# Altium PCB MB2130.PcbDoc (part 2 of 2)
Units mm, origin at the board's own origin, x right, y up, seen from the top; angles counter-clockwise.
Board outline 43 x 51.11 mm, 4 copper layers (Top Layer, Signal Layer 1, Signal Layer 2, Bottom Layer), stack 1.592 mm thick; 94 components, 90 nets, 382 pads, 433 vias.
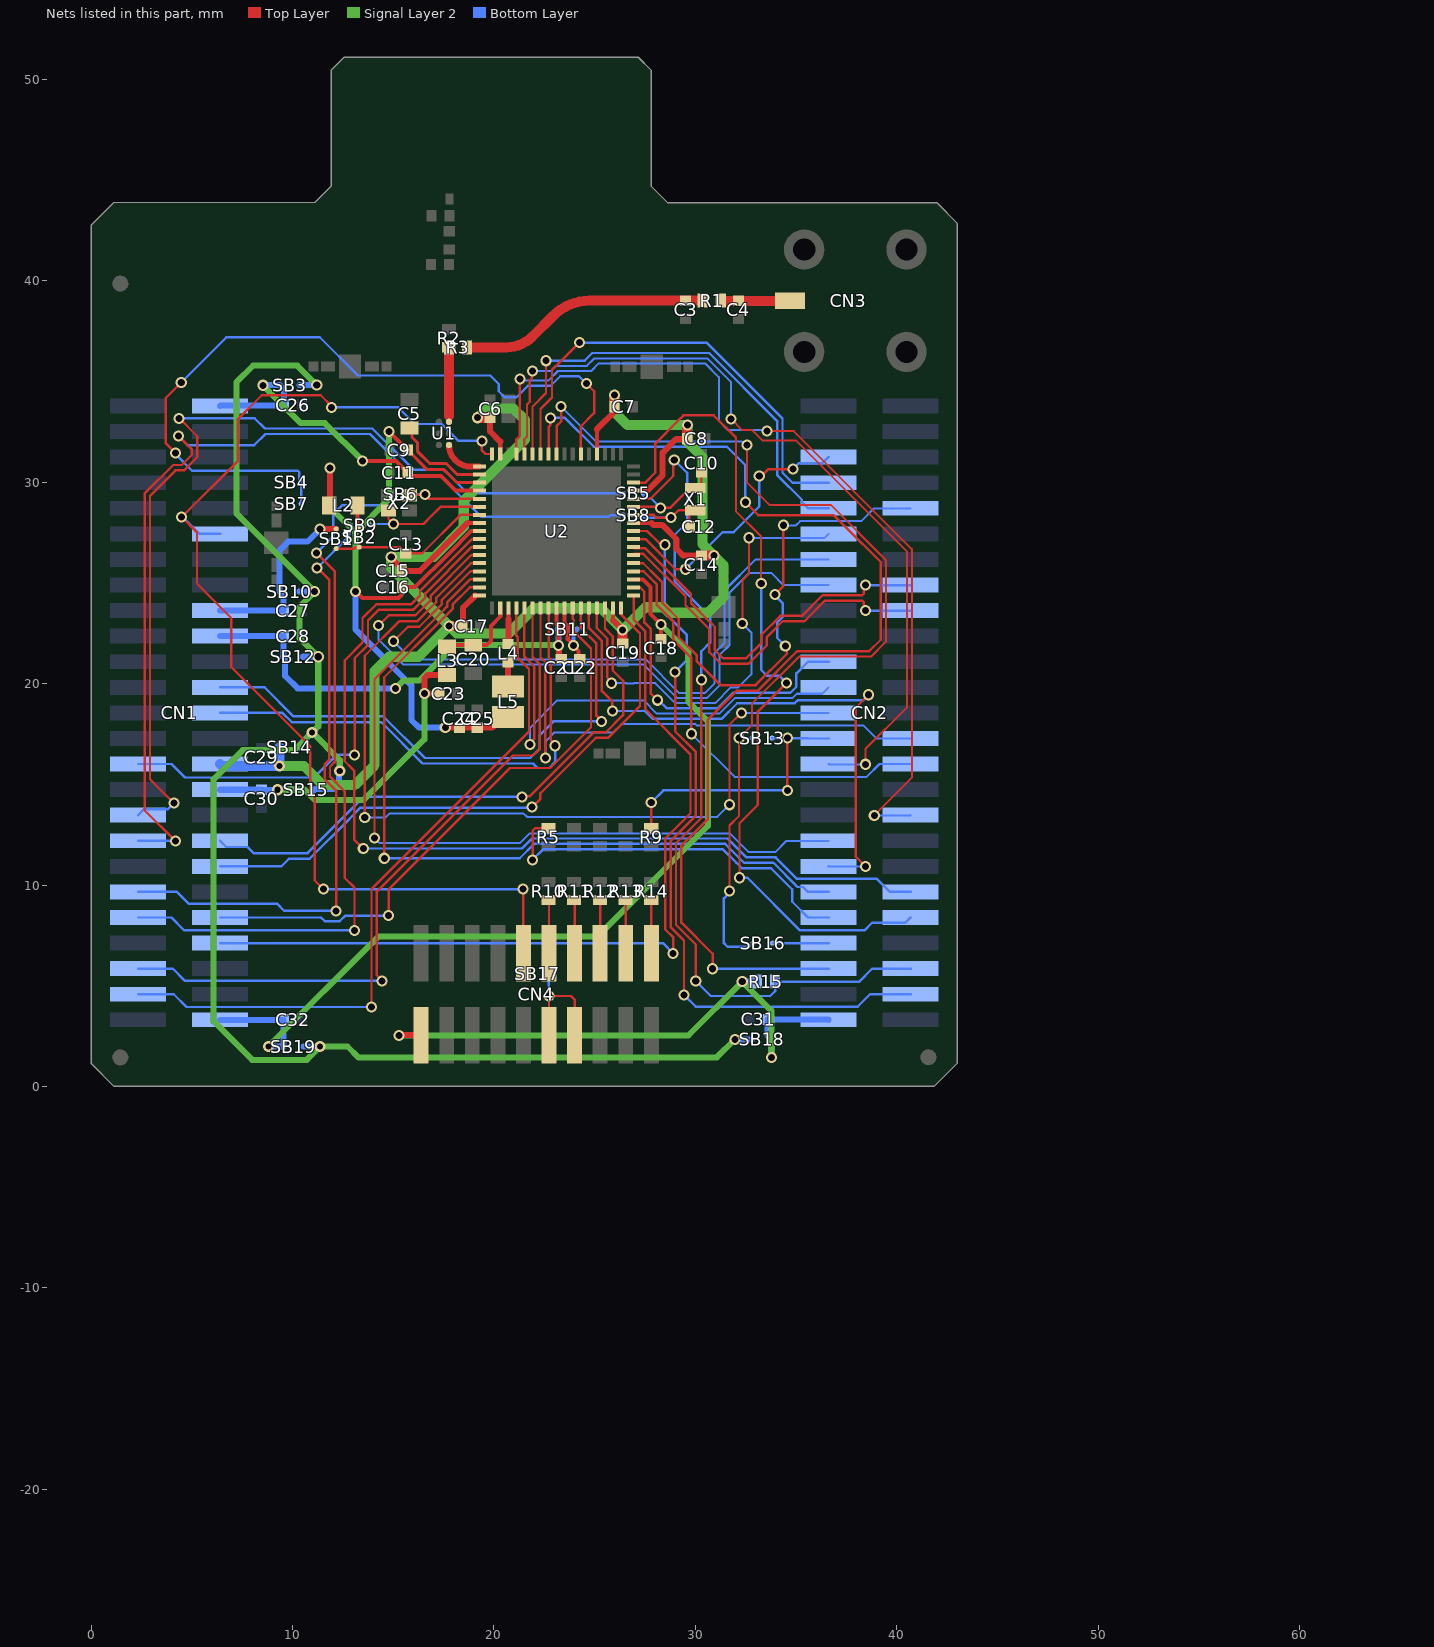
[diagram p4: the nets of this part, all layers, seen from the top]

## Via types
v1: diameter 0.55, hole 0.35, Top Layer to Bottom Layer, tented both sides, 425 vias
v2: diameter 0.55, hole 0.3, Top Layer to Bottom Layer, tented both sides, 8 vias

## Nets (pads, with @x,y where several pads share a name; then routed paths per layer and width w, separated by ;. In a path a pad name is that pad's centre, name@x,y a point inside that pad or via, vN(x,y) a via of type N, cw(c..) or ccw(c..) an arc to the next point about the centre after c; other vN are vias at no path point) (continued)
GPIO11: CN1.24 U2.12 | length 27.6
  Top Layer w0.12: U2.12@24.314,23.755 24.314,22.771 25.091,21.994 25.091,18.411 25.349,18.152 v1(25.349,18.126)
  Bottom Layer w0.12: CN1.24@6.401,19.818 8.613,19.818 10.056,18.376 14.505,18.376 16.574,16.307 21.805,16.307 22.282,16.785 22.282,17.455 22.953,18.126 v1(25.349,18.126)
GPIO12: CN1.26 U2.8 | length 25.7
  Top Layer w0.12: U2.8@22.714,23.755 22.714,21.317 22.822,21.209 22.822,17.589 22.825,17.586 22.825,17.202 23.035,16.991 v1@23.035,16.921
  Bottom Layer w0.12: CN1.26@6.401,18.548 9.501,18.548 9.965,18.085 14.414,18.085 16.462,16.037 21.942,16.037 22.167,15.812 22.746,15.812 23.04,16.106 v1(23.04,16.916)
GPIO14: CN1.29 U2.62 | length 25.6
  Top Layer w0.12: v1(13.081,16.459) 13.081,21.26 13.745,21.924 13.745,23.14 14.269,23.663 15.988,23.663 16.598,24.273 16.598,24.485 18.894,26.78 U2.62@19.289,26.78
  Bottom Layer w0.12: CN1.29@2.331,16.008 3.985,16.008 4.652,15.342 11.074,15.342 12.192,16.459 v1(13.081,16.459)
GPIO15/OSC32_IN: CN1.33 SB5.2 | length 46.8
  Top Layer w0.12: v1(4.109,14.064) 2.922,15.251 2.922,29.326 4.185,30.589 4.608,30.589 5.271,31.253 5.271,32.288 v1@4.377,33.183
  Bottom Layer w0.12: CN1.33@2.331,13.468 2.63,13.767 3.812,13.767 v1(4.109,14.064) ; v1(4.37,33.176) 8.118,33.176 8.625,32.668 13.959,32.668 16,30.627 17.515,30.627 18.687,29.455 26.427,29.455 SB5.2@26.439,29.442
GPIO16/OSC32_OUT: CN1.35 SB8.2 | length 48.4
  Top Layer w0.12: v1(4.184,12.185) 2.652,13.717 2.652,29.438 4.073,30.859 4.496,30.859 5.001,31.365 5.001,31.629 4.336,32.295 v1@4.332,32.295
  Bottom Layer w0.12: CN1.35@2.331,12.198 4.185,12.198 v1@4.191,12.192 ; v1(4.329,32.287) 4.778,31.838 8.089,31.838 8.649,32.398 13.847,32.398 15.943,30.302 17.351,30.302 19.358,28.295 25.715,28.295 25.792,28.372 SB8.2@26.424,28.372
GPIO17: CN1.36 U2.15 | length 28.8
  Top Layer w0.12: v1(21.387,14.376) 21.411,14.401 21.766,14.401 24.942,17.577 25.551,17.577 26.414,18.44 26.414,20.144 25.901,20.658 25.901,22.346 25.514,22.732 U2.15@25.514,23.755
  Bottom Layer w0.12: CN1.36@6.401,12.198 6.711,11.888 7.757,11.888 8.063,11.582 10.745,11.582 12.56,13.397 12.56,13.404 13.533,14.376 v1(21.387,14.376)
GPIO18: CN1.38 U2.17 | length 29.6
  Top Layer w0.12: v1(21.895,13.868) 22.306,14.28 22.306,14.559 25.054,17.307 25.663,17.307 27.254,18.898 27.254,22.486 26.927,22.813 26.354,23.386 26.354,23.715 U2.17@26.314,23.755
  Bottom Layer w0.12: CN1.38@6.401,10.928 9.443,10.928 9.817,11.303 10.466,11.303 10.475,11.312 10.857,11.312 12.83,13.285 12.83,13.292 13.381,13.843 21.151,13.843 21.869,13.843 v1(21.895,13.868)
GPIO21: CN1.42 U2.11 | length 29.6
  Top Layer w0.12: v1@14.783,8.484 14.783,9.8 20.795,15.812 22.795,15.812 24.821,17.837 24.821,21.739 23.976,22.584 23.976,23.152 23.914,23.215 U2.11@23.914,23.755
  Bottom Layer w0.12: CN1.42@6.401,8.388 11.418,8.388 11.603,8.203 12.339,8.203 12.621,8.485 v1@14.783,8.485
  other v1: 14.776,8.478
GPIO22: CN1.44 U2.18 | length 42.3
  Top Layer w0.12: U2.18@26.939,24.38 26.939,23.183 27.524,22.598 27.524,18.728 29.762,16.49 29.762,13.562 28.502,12.301 28.502,7.802 28.909,7.394 v1@28.909,6.615
  Bottom Layer w0.12: CN1.44@6.401,7.118 28.391,7.118 v1(28.902,6.607)
GPIO23: CN1.45 U2.6 | length 35.1
  Top Layer w0.12: v1(14.447,5.238) 14.447,5.267 14.191,5.523 14.191,9.683 20.942,16.434 21.953,16.434 22.282,16.763 22.282,20.953 21.914,21.322 U2.6@21.914,23.755
  Bottom Layer w0.12: CN1.45@2.331,5.848 4.049,5.848 4.659,5.238 v1(14.447,5.238) v1@14.453,5.232
GPIO24: CN1.47 U2.4 | length 35.2
  Top Layer w0.12: v1(13.912,3.944) 13.921,3.952 13.921,9.795 21.742,17.616 21.742,20.73 21.191,21.281 21.191,22.306 21.114,22.383 U2.4@21.114,23.755
  Bottom Layer w0.12: CN1.47@2.331,4.578 4.103,4.578 4.737,3.944 v1(13.912,3.944)
GPIO26: CN2.5 U2.25 | length 13.5
  Top Layer w0.12: U2.25@26.939,27.18 27.523,27.18 29.024,25.679 v1(29.515,25.679) ; v1(33.176,30.308) 33.293,30.308 33.635,30.651 v1(34.842,30.651)
  Bottom Layer w0.12: v1(29.515,25.679) 31.362,27.527 31.908,27.527 33.176,28.795 v1(33.176,30.308) ; v1(34.842,30.651) 35.141,30.95 36.323,30.95 CN2.5@36.621,31.248
GPIO28: CN2.7 U2.45 | length 23.2
  Top Layer w0.12: U2.45@22.314,31.405 22.314,33.642 22.885,34.214 22.885,35.582 v1(24.241,36.937)
  Bottom Layer w0.12: v1(24.241,36.937) 29.216,36.937 29.744,36.937 30.553,36.937 34.331,33.159 34.331,30.475 34.828,29.978 CN2.7@36.621,29.978
GPIO29: CN2.9 U2.46 | length 23.9
  Top Layer w0.12: U2.46@21.914,31.405 21.914,33.753 22.586,34.426 v1(22.586,36.035)
  Bottom Layer w0.12: v1(22.586,36.035) 23.574,36.035 24.504,36.035 24.886,36.417 30.692,36.417 34.061,33.048 34.061,30.363 35.286,29.138 35.286,29.018 35.596,28.708 CN2.9@36.621,28.708
GPIO30: CN2.10 U2.22 | length 25.8
  Top Layer w0.12: U2.22@26.939,25.98 27.416,25.98 28.094,25.302 28.094,25.298 28.364,25.028 28.364,24.011 29.179,23.196 29.179,22.288 30.077,21.39 30.077,21.104 31.254,19.927 32.993,19.927 34.55,21.485 34.55,21.787 v1(34.468,21.869) ; v1(33.96,24.435) 34.373,24.848 v1(34.373,27.865)
  Bottom Layer w0.1: v1(34.373,27.865) 35,27.865 35.202,28.067 38.232,28.067 38.873,28.708 CN2.10@40.691,28.708
  Bottom Layer w0.12: v1(33.96,24.435) 33.96,24.384 34.337,24.007 34.337,23.314 34.059,23.035 34.059,22.278 v1(34.468,21.869)
GPIO31: CN2.11 U2.14 | length 23.1
  Top Layer w0.1: v1(32.332,22.991) 32.332,25.123 32.665,25.456 v1(32.665,27.244)
  Top Layer w0.12: U2.14@25.114,23.755 25.114,22.751 25.631,22.234 25.631,20.306 25.846,20.091 v1(25.846,20.02)
  Bottom Layer w0.1: v1(25.846,20.02) 26.552,20.02 26.562,20.01 26.956,20.01 26.966,20.02 28.011,20.02 29.003,19.028 30.981,19.028 31.764,19.811 32.131,19.811 32.784,20.464 32.784,22.539 v1@32.335,22.988 ; v1(32.665,27.244) 36.427,27.244 CN2.11@36.621,27.438
GPIO33: CN2.13 U2.65 | length 33.7
  Top Layer w0.12: v1(15.014,22.104) 15.719,22.809 15.722,22.809 15.736,22.823 16.294,22.823 17.226,23.756 17.408,23.938 17.408,24.149 18.839,25.58 U2.65@19.289,25.58
  Bottom Layer w0.1: v1(15.014,22.104) 15.908,21.21 27.529,21.21 29.21,19.528 30.468,19.528 30.941,20.002 30.941,21.505 31.449,22.013 31.449,24.624 32.993,26.168 CN2.13@36.621,26.168
GPIO34: CN2.15 U2.63 | length 36.6
  Top Layer w0.12: v1(14.275,22.885) 14.783,23.393 16.1,23.393 16.868,24.162 16.868,24.373 18.875,26.38 U2.63@19.289,26.38
  Bottom Layer w0.1: v1(14.275,22.885) 14.275,22.172 14.546,21.901 ; 14.817,21.629 14.546,21.901 ; 33.863,25.408 33.787,25.484 ; CN2.15@36.621,24.898 34.373,24.898 33.787,25.484 ; 14.546,21.901 15.487,20.96 27.425,20.96 29.107,19.278 30.571,19.278 31.191,19.898 31.191,21.401 31.699,21.909 31.699,24.521 32.663,25.484 33.787,25.484
GPIO37: CN2.21 U2.19 | length 16.3
  Top Layer w0.12: U2.19@26.939,24.78 27.259,24.78 27.349,24.69 27.351,24.69 27.474,24.567 27.474,23.03 27.794,22.71 27.794,19.501 v1(28.118,19.177)
  Bottom Layer w0.12: v1(28.118,19.177) 28.188,19.177 28.597,18.768 31.088,18.768 31.871,19.551 34.724,19.551 35.016,19.844 35.016,20.508 35.596,21.088 CN2.21@36.621,21.088
GPIO39: CN2.23 U2.5 | length 24.1
  Top Layer w0.12: U2.5@21.514,23.755 21.514,21.34 22.012,20.842 22.012,17.271 21.797,17.056 v1(21.797,16.986)
  Bottom Layer w0.1: v1(21.797,16.986) 21.797,17.813 23.151,19.167 27.437,19.167 28.096,18.508 31.196,18.508 31.979,19.291 34.832,19.291 35.039,19.498 36.301,19.498 CN2.23@36.621,19.818
GPIO41: CN2.25 U2.64 | length 43.4
  Top Layer w0.1: v1(31.692,13.988) 31.692,17.951 v1(32.283,18.542)
  Top Layer w0.12: v1(13.585,13.358) 13.585,21.383 15.311,23.108 16.197,23.108 17.114,24.026 17.138,24.05 17.138,24.261 18.857,25.98 U2.64@19.289,25.98
  Bottom Layer w0.1: v1(13.585,13.358) 14.628,13.358 14.834,13.564 21.463,13.564 21.641,13.386 31.09,13.386 v1(31.692,13.988) ; v1(32.283,18.542) 36.615,18.542 CN2.25@36.621,18.548
GPIO42: CN2.27 R9.1 SB13.1 | length 13.7
  Top Layer w0.12: R9.1@27.813,12.82 v1(27.813,14.097) ; v1(34.574,14.701) 34.574,17.284 v1(34.587,17.297)
  Bottom Layer w0.12: v1(27.813,14.097) 28.417,14.701 v1(34.574,14.701) ; SB13.1@33.813,17.297 v1(34.587,17.297) 35.577,17.297 35.596,17.278 CN2.27@36.621,17.278
GPIO43: CN2.28 U2.7 | length 27.1
  Top Layer w0.12: U2.7@22.314,23.743 22.314,21.304 22.552,21.065 22.552,17.477 22.555,17.474 22.555,16.819 v1(22.555,16.307)
  Bottom Layer w0.1: v1(22.555,16.307) 22.555,17.124 23.008,17.577 25.933,17.577 26.344,17.988 27.045,17.988 30.004,17.988 30.068,17.924 38.33,17.924 38.976,17.278 CN2.28@40.691,17.278
GPIO44: CN2.29 U2.47 | length 41.4
  Top Layer w0.1: v1(31.775,33.147) 32.334,32.588 32.836,32.588 33.357,32.068 35.011,32.068 40.506,26.572 40.506,18.813 38.45,16.757 v1(38.45,15.996)
  Top Layer w0.12: U2.47@21.514,31.405 21.514,32.129 21.506,32.137 21.644,32.275 21.644,33.865 21.776,33.998 21.776,35.06 21.884,35.168 21.884,35.492 v1(21.923,35.531)
  Bottom Layer w0.1: v1(21.923,35.531) 22.835,35.531 23.079,35.775 24.611,35.775 24.993,36.157 30.584,36.157 31.775,34.966 v1(31.775,33.147) ; CN2.29@36.621,16.008 36.633,15.996 v1(38.45,15.996)
GPIO45: CN2.30 U2.21 | length 21.6
  Top Layer w0.12: U2.21@26.939,25.58 27.434,25.58 27.764,25.25 27.764,25.246 28.094,24.916 28.094,23.899 28.909,23.084 28.909,22.176 29.807,21.279 v1(29.807,17.513)
  Bottom Layer w0.1: v1(29.807,17.513) 31.953,15.367 38.506,15.367 39.147,16.008 CN2.30@40.691,16.008
GPIO46: CN2.34 U2.48 | length 44.5
  Top Layer w0.1: v1(33.553,32.543) 34.889,32.543 40.756,26.675 40.756,15.331 v1(38.887,13.462)
  Top Layer w0.12: U2.48@21.114,31.405 21.114,32.127 21.282,32.295 21.282,35.048 21.285,35.052 21.285,35.122 v1(21.291,35.128)
  Bottom Layer w0.1: v1(21.291,35.128) 21.363,35.056 22.714,35.056 23.183,35.525 24.832,35.525 25.214,35.907 30.48,35.907 31.166,35.222 31.166,33.045 31.623,32.588 33.508,32.588 v1(33.553,32.543) ; v1(38.887,13.462) 40.685,13.462 CN2.34@40.691,13.468
GPIO47: CN2.35 U2.66 | length 38.8
  Top Layer w0.12: v1(14.07,12.344) 14.07,20.218 17.338,23.486 17.678,23.826 17.678,24.037 18.821,25.18 U2.66@19.289,25.18
  Bottom Layer w0.1: v1(14.07,12.344) 14.329,12.085 21.293,12.085 21.777,12.57 31.707,12.57 32.644,11.633 33.964,11.633 34.529,12.198 CN2.35@36.621,12.198
GPIO49: CN2.37 U2.13 | length 29.8
  Top Layer w0.12: U2.13@24.714,23.755 24.714,22.769 25.361,22.122 25.361,19.631 25.883,19.109 v1(25.883,18.644) ; v1(38.456,10.922) 37.965,11.413 37.965,18.806 v1(38.607,19.448)
  Bottom Layer w0.12: v1(25.883,18.644) 27.493,18.644 27.889,18.248 31.304,18.248 32.083,19.027 32.108,19.027 32.112,19.031 34.939,19.031 35.075,19.167 38.326,19.167 v1(38.607,19.448) ; CN2.37@36.621,10.928 36.628,10.922 v1(38.456,10.922)
GPIO50: CN2.39 U2.67 | length 39
  Top Layer w0.12: v1(14.555,11.328) 14.555,20.321 17.45,23.216 17.948,23.714 17.948,23.926 18.803,24.78 U2.67@19.289,24.78
  Bottom Layer w0.12: v1(14.555,11.328) 21.285,11.328 21.997,12.04 31.488,12.04 32.154,11.373 32.424,11.103 33.874,11.103 35.074,9.904 35.351,9.904 35.596,9.658 CN2.39@36.621,9.658
GPIO51: CN2.40 U2.61 | length 48.2
  Top Layer w0.12: v1(13.513,11.811) 13.054,12.269 13.054,15.688 12.93,15.812 12.929,15.812 12.596,16.145 12.596,21.157 13.475,22.036 13.475,23.252 14.157,23.933 15.876,23.933 16.328,24.385 16.328,24.597 18.912,27.18 U2.61@19.289,27.18
  Bottom Layer w0.12: v1(13.513,11.811) 13.515,11.813 21.388,11.813 21.885,12.31 31.6,12.31 32.092,11.817 32.536,11.373 33.986,11.373 35.054,10.305 39.019,10.305 39.666,9.658 CN2.40@40.691,9.658
GPIO52: CN2.41 R5.1 | length 19
  Top Layer w0.12: v1(21.92,11.252) 21.92,12.693 22.047,12.82 R5.1@22.708,12.82
  Bottom Layer w0.12: v1(21.92,11.252) 22.438,11.77 31.376,11.77 32.043,11.103 32.313,10.833 33.762,10.833 34.812,9.784 34.812,9.173 35.596,8.388 CN2.41@36.621,8.388
GPIO53: CN2.42 U2.32 | length 41.8
  Top Layer w0.1: 32.012,32.221 32.012,28.568 33.274,27.306 v1(33.274,24.968)
  Top Layer w0.12: U2.32@26.939,29.98 26.939,29.97 27.5,29.97 28.004,30.474 28.02,30.49 28.02,31.931 29.121,33.033 29.121,33.035 29.405,33.319 29.407,33.319 29.409,33.32 30.913,33.32 32.012,32.221 ; v1(32.194,10.363) 32.194,13.07 33.108,13.984 33.108,18.622 v1(34.523,20.036)
  Bottom Layer w0.12: v1(32.194,10.363) 32.585,10.363 35.201,7.747 38.404,7.747 38.788,8.131 40.434,8.131 CN2.42@40.691,8.388 ; v1(33.274,24.968) 33.272,24.966 33.272,20.68 33.566,20.386 34.173,20.386 v1(34.523,20.036)
GPIO54: CN2.43 SB16.1 | length 2.8
  Bottom Layer w0.12: SB16.1@33.839,7.112 36.615,7.112 CN2.43@36.621,7.118
GPIO55: CN2.45 U2.44 | length 55.7
  Top Layer w0.12: U2.44@22.714,31.405 22.714,32.742 22.799,32.827 v1(22.799,33.198) ; v1(30.861,5.842) 30.861,6.588 29.312,8.137 29.312,11.966 30.625,13.279 30.625,18.218 32.064,19.657 33.104,19.657 35.057,21.61 38.633,21.61 39.206,22.183 39.206,26.033 37.457,27.783 36.87,28.369 33.125,28.369 v1(32.487,29.007)
  Bottom Layer w0.12: v1(22.799,33.198) 23.528,33.198 24.956,31.769 27.203,31.769 31.565,31.769 32.487,30.847 v1(32.487,29.007) ; v1(30.861,5.842) 36.615,5.842 CN2.45@36.621,5.848
GPIO56: CN2.46 R15.1 U2.30 | length 43.3
  Top Layer w0.12: U2.30@26.939,29.18 27.768,29.18 28.913,30.326 28.913,31.109 v1(28.955,31.109) ; v1(30.023,5.232) 30.023,7.044 29.042,8.025 29.042,12.078 30.302,13.338 v1(30.302,20.193)
  Bottom Layer w0.12: v1(28.955,31.109) 29.597,30.467 29.597,28.014 28.977,27.394 28.977,25.072 30.734,23.315 30.734,22.039 30.302,21.608 v1(30.302,20.193) ; v1(30.023,5.232) 30.767,4.489 33.724,4.489 33.96,4.724 R15.1@33.96,5.207 38.148,5.207 38.79,5.848 CN2.46@40.691,5.848
GPIO57: CN2.48 U2.26 | length 37.9
  Top Layer w0.12: U2.26@26.939,27.58 27.608,27.58 28.208,26.979 28.41,26.979 v1(28.492,26.897) ; v1(29,20.587) 29,17.634 30.032,16.602 30.032,13.45 28.772,12.189 28.772,7.914 29.439,7.247 v1(29.439,4.547)
  Bottom Layer w0.12: v1(28.492,26.897) 28.492,23.517 29.57,22.439 29.57,21.156 v1(29,20.587) ; v1@29.47,4.578 v1(29.439,4.547) 30.023,3.962 38.067,3.962 38.683,4.578 38.891,4.578 CN2.48@40.691,4.578
IPD_in: U1.A1 U2.52 | length 2.1
  Top Layer w0.3: U1.A1@17.769,31.849 ccw(c18.838,31.849) 18.838,30.78 U2.52@19.289,30.78
IPD_out: R2.2 R3.2 U1.A3 | length 3.6
  Top Layer w0.32: U1.A3@17.769,33.003 17.769,33.229
  Top Layer w0.5: 17.769,33.304 R2.2@17.769,36.701
NetC5_2: C5.2 U2.53 | length 4.9
  Top Layer w0.15: C5.2@15.799,32.702 15.921,32.579 15.921,32.245 16.195,31.971 16.195,31.542 16.81,30.927 17.64,30.927 18.187,30.38 U2.53@19.289,30.38
NetC9_1: C9.1 C16.2 C24.1 C25.2 L2.2 L5.2 U2.54 U2.60 | length 40.9
  Top Layer w0.15: C9.1@15.715,31.598 16.686,30.627 17.508,30.627 17.609,30.526 17.616,30.526 18.162,29.98 U2.54@19.289,29.98
  Top Layer w0.2: v1(13.129,24.579) 13.465,24.243 15.264,24.243 15.436,24.415 C16.2@15.436,24.79 16.084,24.79 17.788,26.494 18.873,27.58 U2.60@19.289,27.58 ; v1(14.785,32.528) C9.1@15.715,31.598
  Top Layer w0.3: L2.2@11.822,28.854 11.862,28.894 v1(11.862,30.709) ; v1(17.585,17.813) C24.1@18.288,17.813 C25.2@19.177,17.813 19.913,17.813 20.451,18.351 L5.2@20.701,18.351 L5.2@20.339,18.713
  Signal Layer 2 w0.3: v1(11.862,30.709) 11.862,28.765 13.129,27.498 ; v1(13.129,24.579) 13.129,27.498 ; v1(14.785,32.528) 14.785,29.154 13.129,27.498
  Bottom Layer w0.3: v1(13.129,24.579) 13.129,22.684 15.908,19.905 15.908,18.191 16.286,17.813 v1(17.585,17.813)
NetC13_1: C13.1 SB1.2 SB2.1 U2.58 | length 8.1
  Top Layer w0.12: SB1.2@12.167,26.704 13.054,26.704 13.129,26.779 SB2.1@13.31,26.779 15.316,26.779 C13.1@15.621,26.474 16.439,26.474 18.345,28.38 U2.58@19.289,28.38
NetC20_2: C20.2 L3.1 U2.2 | length 4
  Top Layer w0.2: L3.1@17.787,21.886 17.81,21.909 C20.2@18.974,21.909 19.633,21.909 19.852,22.128 19.852,22.874 20.314,23.336 U2.2@20.314,23.755
NetC22_2: C22.2 SB11.2 U2.10 | length 3.8
  Top Layer w0.2: U2.10@23.514,23.755 23.514,23.01 23.666,22.858 23.666,22.205 23.952,21.919 23.952,21.864 24.207,21.61 24.207,21.422 24.275,21.354 C22.2@24.308,21.354
  Bottom Layer w0.2: v1(23.952,21.895) 23.952,22.419 ; 24.047,22.513 23.952,22.419 ; SB11.2@24.122,22.708 24.122,22.671 23.952,22.502 23.952,22.419
NetCN4_11: CN4.11 CN4.13 SB17.2 | length 6.2
  Top Layer w0.12: v1(22.726,4.489) v1@22.736,4.489 ; v1@22.733,4.496 22.736,4.493 v1@22.736,4.489 ; CN4.11@22.736,2.544 v1@22.736,4.489 ; CN4.13@24.006,2.544 24.006,4.316 23.833,4.489 v1@22.736,4.489
  Bottom Layer w0.12: SB17.2@22.648,5.581 22.648,5.552 22.726,5.474 v1(22.726,4.489)
NetCN4_12: CN4.12 R10.1 | length 2.7
  Top Layer w0.12: R10.1@22.708,9.253 22.736,9.224 CN4.12@22.736,6.614
NetCN4_14: CN4.14 R11.1 | length 2.7
  Top Layer w0.12: R11.1@23.978,9.253 24.006,9.224 CN4.14@24.006,6.614
NetCN4_16: CN4.16 R12.1 | length 2.6
  Top Layer w0.12: R12.1@25.273,9.253 25.276,9.25 CN4.16@25.276,6.614
NetCN4_18: CN4.18 R13.1 | length 2.6
  Top Layer w0.12: R13.1@26.543,9.253 26.546,9.25 CN4.18@26.546,6.614
NetCN4_20: CN4.20 R14.1 | length 2.6
  Top Layer w0.12: R14.1@27.813,9.253 27.816,9.25 CN4.20@27.816,6.614
NetL2_1: L2.1 SB2.2 | length 1.2
  Top Layer w0.2: L2.1@13.222,28.854 13.222,27.841 SB2.2@13.31,27.754 SB2.2@13.31,27.679
NetL4_1: L4.1 U2.3 | length 1.8
  Top Layer w0.2: 20.714,23.202 U2.3@20.714,23.755
  Top Layer w0.3: L4.1@20.701,21.964 20.714,21.977 20.714,23.202
NetL4_2: L4.2 L5.1 | length 1.2
  Top Layer w0.3: L5.1@20.701,19.851 L4.2@20.701,21.064
NetSB3_1: SB3.1 SB10.1 SB12.1 SB14.1 SB15.1 SB18.1 SB19.1 | length 79.6
  Signal Layer 2 w0.3: v1(11.201,34.823) 10.236,35.789 8.038,35.789 7.215,34.966 7.215,28.451 v1(11.1,24.567) 10.338,23.805 10.338,22.276 v1(11.278,21.336) 11.278,17.882 v2(10.973,17.577) ; v2(12.344,15.672) 12.344,16.205 v2(10.973,17.577) ; v1(31.97,2.337) 31.073,1.441 13.27,1.441 12.729,1.981 v2(11.372,1.981) 10.712,1.321 7.997,1.321 6.081,3.237 6.081,15.262 7.522,16.702 10.098,16.702 v2(10.973,17.577)
  Bottom Layer w0.3: SB14.1@10.331,16.84 10.331,16.935 v2(10.973,17.577) ; SB10.1@10.33,24.567 v1(11.1,24.567) ; SB3.1@10.342,34.823 v1@11.201,34.823 ; SB12.1@10.508,21.336 v1(11.278,21.336) ; SB19.1@10.534,1.981 v2(11.372,1.981) ; 11.024,14.68 11.109,14.766 12.023,14.766 12.297,15.039 12.297,15.624 v2(12.344,15.672) ; v1(31.97,2.337) SB18.1@32.812,2.337
NetSB4_2: SB4.2 SB7.2 U2.40 | length 39.2
  Top Layer w0.12: v1(4.191,31.445) 3.708,31.928 3.708,34.198 v1(4.473,34.963) ; U2.40@24.314,31.405 24.314,32.772 24.973,33.431 24.973,34.516 v1(24.589,34.9)
  Bottom Layer w0.12: v1(4.191,31.445) 4.191,31.397 5.02,30.568 10.269,30.568 10.34,30.497 10.34,29.999 SB4.2@10.342,29.997 ; v1(4.473,34.963) 6.713,37.203 11.35,37.203 13.253,35.3 19.818,35.3 20.237,34.881 20.237,34.521 20.544,34.214 21.106,34.214 21.689,34.796 22.821,34.796 23.29,35.265 24.224,35.265 v1(24.589,34.9) ; SB4.2@10.417,29.997 10.424,29.99 10.424,28.937 SB7.2@10.431,28.931
NetSB13_2: SB13.2 SB16.2 U2.43 | length 49.5
  Top Layer w0.1: v1(31.699,9.703) 31.699,12.956 32.182,13.439 v1(32.182,17.297) 32.809,17.925 32.809,18.994 35.164,21.35 38.741,21.35 39.466,22.075 39.466,26.141 36.745,28.862 33.689,28.862 32.559,29.992 v1(32.559,31.841)
  Top Layer w0.12: U2.43@23.114,31.405 23.114,32.792 23.34,33.017 v1(23.34,33.753)
  Bottom Layer w0.1: v1(23.34,33.753) 25.064,32.029 32.275,32.029 32.464,31.841 v1(32.559,31.841) ; v1(32.182,17.297) SB13.2@32.838,17.297
  Bottom Layer w0.12: v1@23.324,33.769 v1(23.34,33.753) ; v1(31.699,9.703) 31.699,9.618 31.42,9.339 31.42,7.117 31.6,6.937 32.689,6.937 SB16.2@32.864,7.112 ; SB13.2@32.832,17.291 SB13.2@32.838,17.297
NRST: CN1.12 CN4.10 U2.51 | length 57.4
  Top Layer w0.12: v1(11.538,9.795) 11.105,10.228 11.105,14.348 10.89,14.563 10.89,16.889 6.954,20.824 6.954,23.26 5.255,24.958 5.255,27.511 v1(4.496,28.27) 7.286,31.061 7.286,33.139 8.47,34.323 11.398,34.323 11.938,33.782 v1(11.938,33.716) ; v1(19.406,32.055) 19.406,31.577 19.577,31.405 U2.51@19.914,31.405 ; v1(21.453,9.795) 21.453,6.627 CN4.10@21.466,6.614
  Bottom Layer w0.12: v1(4.496,28.27) 4.545,28.27 5.376,27.438 CN1.12@6.401,27.438 ; v1(11.538,9.795) v1(21.453,9.795) v1@21.463,9.804 ; v1(11.938,33.716) 15.246,33.716 16.071,32.891 17.406,32.891 18.245,32.052 19.403,32.052 v1(19.406,32.055)
OSC32_IN: C10.2 SB5.1 U2.29 X1.1 | length 5.9
  Top Layer w0.12: U2.29@26.939,28.78 28.218,28.78 v1(28.27,28.727) 28.748,28.727 29.73,29.709 X1.1@29.997,29.709 30.302,29.709 C10.2@30.302,30.487
  Bottom Layer w0.12: SB5.1@27.402,29.455 27.427,29.429 27.427,29.225 27.472,29.18 27.818,29.18 v1(28.27,28.727)
OSC32_OUT: C12.2 SB8.1 U2.28 X1.2 | length 5.9
  Top Layer w0.12: U2.28@26.939,28.38 27.932,28.38 28.069,28.242 28.801,28.242 v1(28.804,28.245) 29.168,28.609 X1.2@29.997,28.609 29.705,28.609 29.705,27.807 C12.2@29.725,27.788
  Bottom Layer w0.12: SB8.1@27.399,28.372 27.399,28.336 27.47,28.265 27.47,28.242 28.801,28.242 v1(28.804,28.245)
OSC_IN: SB9.2 U2.57 X2.3 | length 6.6
  Top Layer w0.12: X2.3@14.766,28.606 14.766,28.181 v1(15.02,27.927) 16.497,27.927 16.939,28.369 17.224,28.654 17.35,28.78 U2.57@19.289,28.78
  Bottom Layer w0.12: SB9.2@13.86,27.864 13.867,27.864 13.93,27.927 v1(15.02,27.927)
OSC_IN_ext: CN1.39 SB9.1 | length 30.6
  Top Layer w0.12: v1@11.232,25.749 11.817,25.164 11.817,16.213 11.589,15.985 11.589,15.27 12.161,14.698 v1(12.161,8.711)
  Bottom Layer w0.12: CN1.39@2.331,9.658 4.261,9.658 4.841,9.078 9.228,9.078 9.588,8.718 v1@12.168,8.718 ; v1(11.224,25.742) 12.81,27.328 SB9.1@12.81,27.864
OSC_OUT: SB6.2 U2.56 X2.1 | length 4.4
  Top Layer w0.12: X2.1@15.816,29.356 15.847,29.388 v1(16.586,29.388) 16.794,29.18 U2.56@19.289,29.18
  Bottom Layer w0.12: SB6.2@15.766,29.413 15.779,29.4 16.573,29.4 v1(16.586,29.388)
OSC_OUT_ext: CN1.41 SB6.1 | length 36.3
  Top Layer w0.12: v1@11.189,26.487 12.087,25.589 12.087,16.101 11.859,15.873 11.859,15.382 12.596,14.645 12.596,10.349 13.076,9.869 v1(13.076,7.745)
  Bottom Layer w0.12: CN1.41@2.331,8.388 3.981,8.388 4.617,7.752 v1@13.083,7.752 ; v1(11.182,26.48) 12.028,27.326 12.028,28.418 12.464,28.854 14.357,28.854 14.804,29.301 14.804,29.401 SB6.1@14.791,29.413
SMA-path: C3.2 R1.1 R3.1 | length 12.5
  Top Layer w0.5: R3.1@18.665,36.701 20.621,36.701 ccw(c20.621,38.529) 21.914,37.237 22.951,38.273 cw(c24.747,36.477) 24.747,39.017 C3.2@29.515,39.017 30.353,39.017 R1.1@30.36,39.024
SMA_in: C4.2 CN3.1 R1.2 | length 3.4
  Top Layer w0.5: R1.2@31.275,39.01 33.029,39.01 34.693,39.01 CN3.1@34.698,39.014
USB_HS_N: CN2.18 U2.23 | length 18.9
  Top Layer w0.12: U2.23@26.939,26.38 cw(c27.004,26.38) 27.004,26.445 27.414,26.445 29.515,24.344 29.515,23.893 30.694,22.713 30.694,21.563 31.268,20.99 32.637,20.99 33.553,21.906 33.553,22.314 34.337,23.098 35.416,23.098 36.444,24.125 38.293,24.125 38.364,24.055 38.364,23.706 v1(38.441,23.628)
  Bottom Layer w0.12: v1(38.441,23.628) CN2.18@40.691,23.628
USB_HS_P: CN2.16 U2.24 | length 18.9
  Top Layer w0.12: U2.24@26.939,26.78 ccw(c27.004,26.78) 27.004,26.715 27.526,26.715 29.785,24.456 29.785,24.005 30.695,23.094 30.806,22.983 30.964,22.825 30.964,21.675 31.379,21.26 32.525,21.26 33.283,22.018 33.283,22.426 34.225,23.368 35.305,23.368 36.332,24.395 38.293,24.395 38.364,24.465 38.364,24.814 v1(38.441,24.892)
  Bottom Layer w0.12: v1(38.441,24.892) 40.685,24.892 CN2.16@40.691,24.898
VDD1: C11.1 C26.2 CN1.2 SB3.2 U2.55 | length 18
  Top Layer w0.2: v1(13.483,31.064) 15.131,31.064 C11.1@15.715,30.48 15.715,30.457 15.87,30.302 17.374,30.302 18.096,29.58 U2.55@19.289,29.58
  Top Layer w0.3: v1@13.479,31.06 v1(13.483,31.064)
  Signal Layer 2 w0.3: v1(8.53,34.816) 10.406,32.94 11.607,32.94 v1(13.483,31.064)
  Bottom Layer w0.3: CN1.2@6.401,33.788 6.423,33.81 9.547,33.81 C26.2@9.569,33.832 9.569,34.621 SB3.2@9.367,34.823 v1@8.538,34.823
VDD3: C27.2 CN1.18 SB1.1 SB10.2 | length 9.5
  Top Layer w0.3: v1(11.373,27.679) SB1.1@12.167,27.679
  Bottom Layer w0.3: CN1.18@6.402,23.628 C27.2@9.557,23.627 ; C27.2@9.557,23.627 9.557,24.391 9.382,24.567 SB10.2@9.355,24.567 9.355,26.618 9.785,27.047 10.742,27.047 v1(11.373,27.679)
VDD4: C6.1 C7.1 C8.1 C14.1 C15.1 C17.1 C19.1 C29.2 CN1.30 SB14.2 U2.16 U2.27 U2.31 U2.38 U2.50 U2.59 U2.68 | length 92.9
  Top Layer w0.2: 18.708,27.98 U2.59@19.289,27.98 ; U2.68@19.063,24.371 19.28,24.371 U2.68@19.289,24.38 ; U2.50@20.314,31.405 20.314,32.018 ; U2.38@25.114,31.405 25.114,32.633 ; 25.914,23.14 U2.16@25.914,23.755 ; U2.27@26.939,27.98 27.823,27.98 ; U2.31@26.939,29.58 27.619,29.58
  Top Layer w0.3: v1(14.901,26.294) 14.901,26.235 15.436,25.7 C15.1@15.436,25.603 ; C15.1@15.487,25.603 16.331,25.603 18.708,27.98 ; C17.1@18.422,22.86 18.474,22.912 18.474,23.783 U2.68@19.063,24.371 ; v1@19.177,33.198 v1(19.184,33.205) ; C6.1@19.807,33.205 19.807,32.525 20.314,32.018 ; 25.114,32.633 26.014,33.533 C7.1@26.014,33.753 ; 25.914,23.14 26.391,22.664 v1(26.391,22.657) ; v1(25.987,34.344) v1@25.991,34.339 ; 27.619,29.58 28.364,30.325 28.38,30.341 28.38,31.473 29.064,32.156 C8.1@29.598,32.156 ; 27.823,27.98 27.92,27.882 28.353,27.882 29.067,27.168 29.067,26.693 29.402,26.358 C14.1@30.302,26.358 ; v1@29.598,32.826 v1(29.606,32.834)
  Top Layer w0.5: v1(17.78,22.86) C17.1@18.422,22.86 ; v1(19.184,33.205) C6.1@19.807,33.205 ; C7.1@25.991,33.757 v1@25.991,34.339 ; C19.1@26.391,21.989 v1(26.391,22.657) ; C8.1@29.598,32.156 v1@29.598,32.826 ; C14.1@30.302,26.358 v1(30.926,26.358)
  Signal Layer 2 w0.5: v2(9.354,15.908) 10.569,15.908 11.516,14.961 13.087,14.961 14.078,15.951 14.078,20.625 14.789,21.336 16.256,21.336 v1(17.78,22.86) ; v1(19.184,33.205) 19.198,33.205 19.648,33.655 20.978,33.655 21.552,33.081 21.552,32.13 18.501,29.079 18.501,27.773 17.021,26.294 v1(14.901,26.294) 14.901,25.739 v1(17.78,22.86) ; v1(25.987,34.344) 25.987,33.478 26.631,32.834 v1(29.606,32.834) 29.606,31.996 30.347,31.255 30.347,26.936 31.394,25.889 31.394,24.29 30.626,23.521 28.697,23.521 28.424,23.794 27.528,23.794 v1(26.391,22.657) 26.391,22.664 25.312,23.743 21.977,23.743 20.735,22.501 18.139,22.501 v1(17.78,22.86)
  Bottom Layer w0.5: CN1.30@6.401,16.008 6.497,15.913 8.453,15.913 C29.2@8.458,15.908 v2(9.354,15.908) 9.354,16.839 SB14.2@9.356,16.84
VDD5: C23.1 C30.2 CN1.32 L3.2 SB15.2 | length 17.5
  Top Layer w0.3: C23.1@17.279,19.507 v1(16.545,19.507) 16.545,20.257 16.721,20.433 L3.2@17.678,20.433
  Signal Layer 2 w0.3: v2(9.246,14.732) 10.605,14.732 11.105,14.232 13.537,14.232 16.545,17.24 v1(16.545,19.507)
  Bottom Layer w0.3: CN1.32@6.401,14.738 6.408,14.732 8.451,14.732 C30.2@8.458,14.725 8.462,14.728 9.242,14.728 v2(9.246,14.732) SB15.2@10.168,14.732
VDD14: C31.2 CN2.49 CN4.1 R15.2 SB18.2 | length 29.4
  Top Layer w0.3: v1@15.289,2.544 CN4.1@16.386,2.544
  Signal Layer 2 w0.3: v1(15.281,2.537) 29.661,2.537 v1(32.332,5.207) 33.775,3.764 v1(33.775,1.441)
  Bottom Layer w0.3: v1(32.332,5.207) R15.2@33.06,5.207 ; v1@33.782,1.448 33.782,2.332 SB18.2@33.787,2.337 33.585,2.539 C31.2@33.585,3.327 33.594,3.318 36.612,3.318 CN2.49@36.621,3.308
VDDA: C21.2 C28.2 CN1.20 SB11.1 SB12.2 U2.9 | length 23.3
  Top Layer w0.2: U2.9@23.114,23.755 23.114,22.915 23.199,22.83 v1(23.199,21.895)
  Top Layer w0.3: v1(23.199,21.895) 23.238,21.856 23.238,21.332 C21.2@23.343,21.227
  Signal Layer 2 w0.3: v1(15.116,19.763) 15.502,20.149 16.295,20.149 18.055,21.909 v1@23.185,21.909
  Bottom Layer w0.3: CN1.20@6.401,22.358 6.405,22.355 9.554,22.355 C28.2@9.558,22.352 9.558,21.36 SB12.2@9.533,21.336 9.633,21.236 9.633,20.379 10.249,19.763 v1(15.116,19.763) ; SB11.1@23.147,22.708 23.199,22.655 v1(23.199,21.895)
VDDUSB: C18.1 C32.2 CN1.50 SB19.2 U2.20 | length 46.3
  Top Layer w0.2: U2.20@26.939,25.18 27.392,25.18 27.784,24.788 27.784,23.448 v1(28.296,22.936) C18.1@28.296,22.218
  Signal Layer 2 w0.3: v2(8.802,1.981) 14.259,7.439 25.125,7.439 30.619,12.933 30.619,18.126 29.667,19.078 29.667,21.565 v1(28.296,22.936)
  Bottom Layer w0.3: CN1.50@6.401,3.308 6.402,3.307 9.557,3.307 C32.2@9.558,3.306 SB19.2@9.559,1.981 ; v2(8.802,1.981) SB19.2@9.559,1.981
pads on no net: CN1.3 CN1.4 CN1.5 CN1.10 CN1.11 CN1.16 CN1.27 CN1.43 CN1.48 CN2.1 CN2.3 CN2.4 CN2.6 CN2.17 CN2.19 CN2.24 CN2.31 CN2.33 CN2.36 CN2.47 CN4.7 Designator1.1 MIRE1.1 MIRE2.1 MIRE3.1 MIRE4.1 MIRE5.1 MIRE6.1

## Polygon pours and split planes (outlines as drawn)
GND on Top Layer "GND_L01_P018" (solid, remove dead copper, pour order 18): -3.886,43.886 44.094,43.886 44.094,-0.965 -3.886,-0.965
no net on Top Layer "RF_OUT" (solid, pour order 5): 18.071,36.862 17.99,36.589 17.692,36.58 17.626,36.837
GND on Signal Layer 1 "Internal 1-GND" (solid, remove dead copper, pour order 13): 33.58,39.534 33.58,39.776 35.789,39.776 35.789,38.278 33.579,38.278 33.579,38.494 24.749,38.494 ccw(c24.749,36.482) 23.325,37.905 22.327,36.906 cw(c20.684,38.548) 20.684,36.226 18.237,36.226 18.237,31.953 ccw(c18.999,31.953) 18.999,31.191 19.761,31.191 19.761,30.455 18.898,30.455 cw(c18.898,32.057) 17.295,32.057 17.295,43.886 -2.431,43.886 -2.431,-1.603 45.042,-1.603 45.042,43.886 18.237,43.886 18.237,37.176 20.422,37.176 ccw(c20.422,38.867) 21.618,37.671 22.737,38.79 cw(c24.533,36.994) 24.533,39.534 24.78,39.534
GND on Bottom Layer "Bottom Layer-GND" (solid, remove dead copper, pour order 7): -2.082,43.886 45.441,43.886 45.441,-1.454 -2.082,-1.454
GND on Signal Layer 2 "Internal 2-GND" (solid, remove dead copper, pour order 11): -5.171,43.886 46.823,43.886 46.823,-0.705 -5.171,-0.705

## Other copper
Top Layer:
  pour cut-out: 33.757,39.624 35.662,39.624 35.662,38.405 33.757,38.405
  text "1" at 1.286,41.647 h2
Signal Layer 1:
  text "2" at 2.536,41.647 h2
Signal Layer 2:
  text "3" at 4.786,41.647 h2
Bottom Layer:
  text "4" at 6.286,41.647 h2
Multi-Layer:
  pour cut-out: 0.786,43.397 0.786,41.147 6.886,41.147 6.886,43.397

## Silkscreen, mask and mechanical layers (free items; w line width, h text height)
Top Overlay:
  lines w0.05: -0.592,0 1.139,0 ; 0,-0.5 0,1.139
  text "L" at 1.959,36.409 h7.62
  text "J" at 3.404,5.004 h12
  text "K" at 35.052,2.667 h7.62
  text "MB2130A" at 2.769,1.988 h2.5
Bottom Overlay:
  text "G" at 37.846,37.77 h5.5
  text "C" at 15.926,37.287 h7.62
  text "I" at 22.747,37.287 h7.62
  text "E" at 30.836,37.287 h7.62
  text "H" at 8.56,37.211 h7.62
Top Solder:
  rectangle: 1.036,41.397 6.636,43.147
Bottom Solder:
  rectangle: 1.036,41.397 6.636,43.147
M1-Board Shape:
  the board outline again, w0.1
Drill Drawing:
  drawing of 219 lines, arcs and shapes, not listed
  text "Layer" at 63.011,56.263 h1.8
  text "Name" at 70.546,56.263 h1.8
  text "Material" at 85.116,56.263 h1.8
  text "Thickness" at 98.947,56.263 h1.8
  text "Constant" at 109.701,56.263 h1.8
  text "Board Layer Stack" at 119.656,56.263 h1.8
  text "Top Overlay" at 70.546,52.663 h1.8
  text "Top Solder" at 70.546,49.063 h1.8
  text "Solder Resist" at 85.116,49.063 h1.8
  text "0.79mil" at 98.947,49.063 h1.8
  text "3.5" at 109.701,49.063 h1.8
  text "1" at 63.011,45.463 h1.8
  text "Top Layer" at 70.546,45.463 h1.8
  text "2.76mil" at 98.946,45.463 h1.8
  text "Dielectric 1" at 70.546,41.863 h1.8
  text "1080HR RC68" at 85.116,41.863 h1.8
  text "2.99mil" at 98.946,41.863 h1.8
  text "4.2" at 109.701,41.863 h1.8
  text "2" at 63.01,38.263 h1.8
  text "Signal Layer 1" at 70.546,38.263 h1.8
  text "1.38mil" at 98.947,38.263 h1.8
  text "Dielectric 2" at 70.546,34.663 h1.8
  text "FR4" at 85.116,34.663 h1.8
  text "48.43mil" at 98.947,34.663 h1.8
  text "4.5" at 109.701,34.663 h1.8
  text "3" at 63.011,31.063 h1.8
  text "Signal Layer 2" at 70.546,31.063 h1.8
  text "1.38mil" at 98.947,31.063 h1.8
  text "Dielectric 3" at 70.546,27.463 h1.8
  text "1080HR RC68" at 85.116,27.463 h1.8
  text "2.99mil" at 98.946,27.463 h1.8
  text "4.2" at 109.701,27.463 h1.8
  text "4" at 63.011,23.863 h1.8
  text "Bottom Layer" at 70.546,23.863 h1.8
  text "2.76mil" at 98.946,23.863 h1.8
  text "Bottom Solder" at 70.546,20.263 h1.8
  text "Solder Resist" at 85.116,20.263 h1.8
  text "0.79mil" at 98.947,20.263 h1.8
  text "3.5" at 109.701,20.263 h1.8
  text "Bottom Overlay" at 70.546,16.663 h1.8
  text "Symbol" at 63.415,11.754 h2.16
  text "Count" at 71.866,11.754 h2.16
  text "Hole Size" at 80.669,11.754 h2.16
  text "Plated" at 96.225,11.754 h2.16
  text "Hole Type" at 103.645,11.754 h2.16
  text "Drill Layer Pair" at 114.446,11.754 h2.16
  text "Via/Pad" at 134.892,11.754 h2.16
  text "Pad Shape" at 143.741,11.754 h2.16
  text "Template" at 155.302,11.754 h2.16
  text "Description" at 168.476,11.754 h2.16
  text "8" at 71.866,8.029 h1.8
  text "11.81mil (0.30mm)" at 80.669,8.029 h1.8
  text "PTH" at 96.225,8.029 h1.8
  text "Round" at 103.645,8.029 h1.8
  text "Top Layer - Bottom Layer" at 114.446,8.029 h1.8
  text "Via" at 134.892,8.029 h1.8
  text "Rounded" at 143.741,8.029 h1.8
  text "v55h30m0mx0" at 155.302,8.029 h1.8
  text "425" at 71.866,4.305 h1.8
  text "13.78mil (0.35mm)" at 80.669,4.305 h1.8
  text "PTH" at 96.225,4.305 h1.8
  text "Round" at 103.645,4.305 h1.8
  text "Top Layer - Bottom Layer" at 114.446,4.305 h1.8
  text "Via" at 134.892,4.305 h1.8
  text "Rounded" at 143.741,4.305 h1.8
  text "v55h35m0mx0" at 155.302,4.305 h1.8
  text "4" at 71.866,0.58 h1.8
  text "43.31mil (1.10mm)" at 80.669,0.58 h1.8
  text "PTH" at 96.225,0.58 h1.8
  text "Round" at 103.645,0.58 h1.8
  text "Top Layer - Bottom Layer" at 114.446,0.58 h1.8
  text "Pad" at 134.892,0.58 h1.8
  text "Rounded" at 143.741,0.58 h1.8
  text "c200h110m210" at 155.302,0.58 h1.8
  text "437 Total" at 71.866,-3.144 h1.8

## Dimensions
1.139,0 to 1.122,43.891 on M2-Board Dimensions
0,42.769 to 43,42.873 on M2-Board Dimensions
